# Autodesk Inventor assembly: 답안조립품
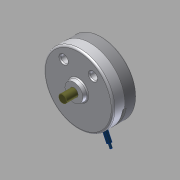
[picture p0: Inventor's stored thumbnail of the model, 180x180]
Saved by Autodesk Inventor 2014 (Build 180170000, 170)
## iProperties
Created: 2015-06
Part Number: 답안조립품
Document SubType Name: Assembly
Designer: MYHOME
Author: MYHOME
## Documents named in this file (10)
- C:\Documents and Settings\MYHOME\바탕 화면\450631V1044\450631V1044\답안조립품.iam
- C:\Documents and Settings\MYHOME\바탕 화면\450631V1044\450631V1044\본체.ipt
- C:\Documents and Settings\MYHOME\바탕 화면\450631V1044\450631V1044\덮개.ipt
- C:\Documents and Settings\MYHOME\바탕 화면\450631V1044\450631V1044\베어링62_22.ipt
- C:\Documents and Settings\MYHOME\바탕 화면\450631V1044\450631V1044\축.ipt
- C:\Documents and Settings\MYHOME\바탕 화면\450631V1044\450631V1044\평행핀.ipt
- C:\Documents and Settings\MYHOME\바탕 화면\450631V1044\450631V1044\M10x35.ipt
- C:\Documents and Settings\MYHOME\바탕 화면\450631V1044\450631V1044\멈춤링.ipt
- C:\Documents and Settings\MYHOME\바탕 화면\450631V1044\450631V1044\슬라이더2.ipt
- C:\Documents and Settings\MYHOME\바탕 화면\450631V1044\450631V1044\슬라이더.ipt
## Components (7 placed, 4 different names)
1. KS B 2023 62/22 - 22 x 50 x 14:1
2. KS B 2023 62/22 - 22 x 50 x 14:2
3. KS B 1320 B B 5 x  20:1
4. KS B 1003 - 미터 M 10 x 35:1
5. KS B 1336 22 x 1.2:1
6. KS B 1003 - 미터 M 10 x 35:2
7. KS B 1336 22 x 1.2:2
